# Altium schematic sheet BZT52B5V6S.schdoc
size 127 x 101 mm
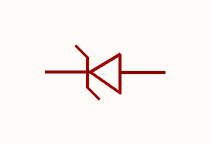
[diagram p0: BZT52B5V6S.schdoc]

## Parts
D?  bzt52b5v6s_c78577  [SOD-323_L1.8-W1.3-LS2.5-RD]  (value not drawn)

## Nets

Not connected (* = marked no-connect by the designer): D? 1(K) 2(A)

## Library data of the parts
D? = bzt52b5v6s_c78577: 二极管配置:1个独立式;稳压值(标称值):5.6V;稳压值(范围值):5.49V~5.71V;耗散功率(Pd):200mW;; Manufacturer: CJ(江苏长电/长晶); AddInBom: yes; ModelId: db63db13d9e342eb939127d413d6200b; ModelTransform: 104.3305,51.181,0,0,0,0,0,-0.004,0; Diode Configuration: 1个独立式; Zener Voltage(Nom): 5.6V; Reverse Leakage Current (Ir): 1uA; Pd - Power Dissipation: 200mW; Impedance(Zzt): 40Ω; Impedance(Zzk): 400Ω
